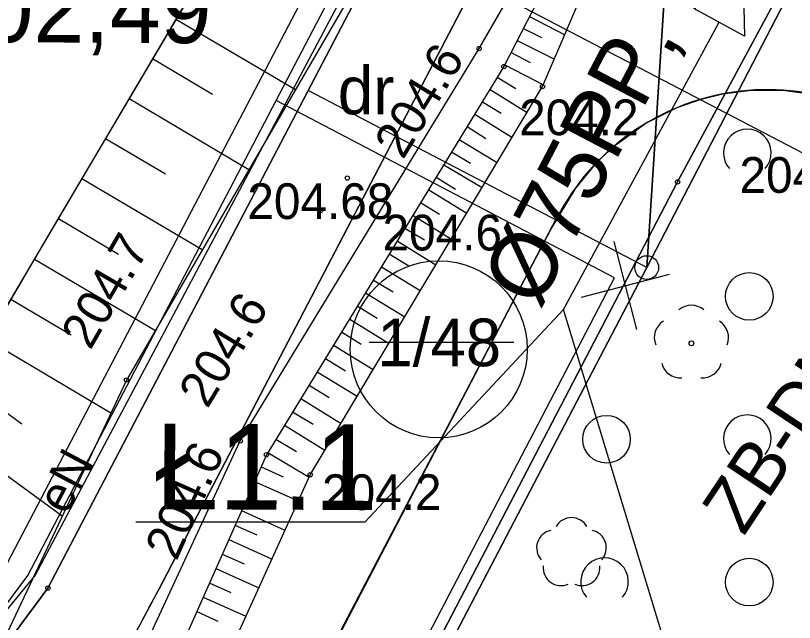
# Model space of a CAD drawing. Extents: x 6512606 to 6513006, y 6022524 to 6022728.
# Drawn here: x 6512715.61 to 6512731.97, y 6022586.93 to 6022599.67 of the extents above; entities that cross this region are included whole.
import ezdxf

# ---------------------------------------------------------------- set-up
doc = ezdxf.new("R2010")
doc.units = 0
for name, color, linetype in [('000 Inne (niezydentyfikowane)', 7, 'Continuous'), ('20', 7, 'Continuous'), ('202-punkt graniczny', 7, 'Continuous'), ('203-punkt graniczny', 7, 'Continuous'), ('210-oznaczenie konturu użytku gruntowego', 7, 'Continuous'), ('211-numer działki ewidencyjnej', 7, 'Continuous'), ('217-kontur klasyfikacyjny', 7, 'Continuous'), ('218-kontur użytku gruntowego', 7, 'Continuous'), ('219-działka ewidencyjna', 7, 'Continuous'), ('3', 7, 'Continuous'), ('4', 7, 'Continuous'), ('6', 7, 'Continuous'), ('926-Drzewo liściaste niepomierzone', 7, 'Continuous'), ('Default', 7, 'Continuous'), ('drzewo liściaste (punkt)', 7, 'Continuous'), ('E_OSW_KABLE', 7, 'Continuous'), ('jezdnia', 7, 'Continuous'), ('kolor_kostka_bet', 7, 'Continuous'), ('kolor_sc_rowerowa', 7, 'Continuous'), ('Level 47', 7, 'Continuous'), ('maxp_kan_deszczowa', 7, 'Continuous'), ('maxp_likwidacje', 7, 'Continuous'), ('maxp_obrzeże', 7, 'Continuous'), ('maxp_ramka_2', 7, 'Continuous'), ('ogrodzenie trwałe', 7, 'Continuous'), ('pikieta naturalna', 7, 'Continuous'), ('pikieta naturalna-Atr2', 7, 'Continuous'), ('pikieta sztuczna', 7, 'Continuous'), ('pikieta sztuczna-Atr2', 7, 'Continuous'), ('przewód elektroenergetyczny (linia)', 7, 'Continuous'), ('przewód elektroenergetyczny (linia)-Atr1', 7, 'Continuous'), ('punkt wysokościowy naturalny', 7, 'Continuous'), ('punkt wysokościowy naturalny-Atr2', 7, 'Continuous'), ('skarpa nieumocniona', 7, 'Continuous'), ('zadrzewienie  zakrzewienie', 7, 'Continuous')]:
    doc.layers.add(name, color=color, linetype=linetype)

# ---------------------------------------------------------------- blocks, each defined once
blk = doc.blocks.new('203')
at = {"layer": 'Default'}
blk.add_circle((0, 0), 0.45, dxfattribs=at)
blk = doc.blocks.new('202')
at = {"layer": 'Default'}
blk.add_circle((0, 0), 2.5, dxfattribs=at)
blk = doc.blocks.new('PW01')
at = {"layer": 'Default'}
blk.add_circle((0, 0), 0.45, dxfattribs=at)
blk = doc.blocks.new('926')
at = {"layer": 'Default'}
for centre, start, end in [((0, 3.75), 30.147, 149.853), ((-3.57, 1.16), 102.147, 221.853), ((3.57, 1.16), 318.147, 77.853), ((-2.2, -3.03), 174.147, 293.853), ((2.2, -3.03), 246.147, 5.853)]:
    blk.add_arc(centre, 3.75, start, end, dxfattribs=at)
blk = doc.blocks.new('OP021')
at = {"layer": 'Default'}
blk.add_circle((0, 0), 0.5, dxfattribs=at)
for centre, start, end in [((0, 4), 49.272, 130.728), ((-3.8, 1.24), 121.308, 202.548), ((3.8, 1.24), 337.452, 58.692), ((-2.35, -3.24), 193.221, 274.871), ((2.35, -3.24), 265.129, 346.779)]:
    blk.add_arc(centre, 4, start, end, dxfattribs=at)
blk = doc.blocks.new('OTZK1')
at = {"layer": 'Default'}
blk.add_circle((0, 0), 5, dxfattribs=at)
blk = doc.blocks.new('OTZK2')
at = {"layer": 'Default'}
blk.add_arc((0, 0), 5, 318.85, 221.162, dxfattribs=at)

msp = doc.modelspace()

# ---------------------------------------------------------------- linework, layer by layer
msp.add_lwpolyline([(6512728.87, 6022594.38), (6512721.76, 6022598.101)])
at = {"layer": '000 Inne (niezydentyfikowane)'}
for p, q in [((6512718.98, 6022599.6), (6512721.49, 6022598.12)), ((6512718.49, 6022598.77), (6512719.75, 6022598.02)), ((6512718, 6022597.93), (6512720.51, 6022596.44)), ((6512717.5, 6022597.09), (6512718.76, 6022596.35)), ((6512717, 6022596.25), (6512719.53, 6022594.76)), ((6512716.51, 6022595.41), (6512717.77, 6022594.66)), ((6512716.01, 6022594.56), (6512718.55, 6022593.06)), ((6512715.51, 6022593.72), (6512716.78, 6022592.97)), ((6512715.01, 6022592.87), (6512717.61, 6022591.33)), ((6512714.43, 6022592.05), (6512715.74, 6022591.1)), ((6512713.81, 6022591.19), (6512716.59, 6022589.17))]:
    msp.add_line(p, q, dxfattribs=at)
for points in [[(6512726.41, 6022599.65), (6512727.15, 6022599.27)], [(6512726.28, 6022599.4), (6512726.66, 6022599.21)], [(6512726.15, 6022599.15), (6512726.93, 6022598.76)], [(6512726.02, 6022598.9), (6512726.42, 6022598.69)], [(6512725.89, 6022598.64), (6512726.7, 6022598.22)], [(6512725.73, 6022598.38), (6512726.12, 6022598.14)], [(6512725.58, 6022598.12), (6512726.36, 6022597.64)], [(6512725.42, 6022597.86), (6512725.81, 6022597.62)], [(6512725.26, 6022597.6), (6512726.04, 6022597.12)], [(6512725.1, 6022597.34), (6512725.49, 6022597.09)], [(6512724.93, 6022597.07), (6512725.73, 6022596.59)], [(6512724.77, 6022596.81), (6512725.17, 6022596.57)], [(6512724.61, 6022596.54), (6512725.41, 6022596.06)], [(6512724.45, 6022596.28), (6512724.85, 6022596.03)], [(6512724.29, 6022596.01), (6512725.09, 6022595.52)], [(6512724.12, 6022595.75), (6512724.52, 6022595.5)], [(6512723.96, 6022595.48), (6512724.77, 6022594.98)], [(6512723.79, 6022595.21), (6512724.2, 6022594.96)], [(6512723.63, 6022594.94), (6512724.44, 6022594.44)], [(6512723.46, 6022594.67), (6512723.87, 6022594.42)], [(6512723.3, 6022594.4), (6512724.11, 6022593.9)], [(6512723.13, 6022594.12), (6512723.54, 6022593.87)], [(6512722.96, 6022593.85), (6512723.79, 6022593.35)], [(6512722.79, 6022593.58), (6512723.21, 6022593.32)], [(6512722.63, 6022593.3), (6512723.46, 6022592.79)], [(6512722.46, 6022593.03), (6512722.87, 6022592.77)], [(6512722.29, 6022592.75), (6512723.12, 6022592.24)], [(6512722.12, 6022592.47), (6512722.54, 6022592.21)], [(6512721.95, 6022592.19), (6512722.79, 6022591.68)], [(6512721.78, 6022591.91), (6512722.2, 6022591.65)], [(6512721.6, 6022591.63), (6512722.45, 6022591.11)], [(6512721.43, 6022591.35), (6512721.86, 6022591.09)], [(6512721.26, 6022591.07), (6512722.11, 6022590.55)], [(6512721.08, 6022590.78), (6512721.51, 6022590.52)], [(6512720.91, 6022590.5), (6512721.78, 6022589.98)], [(6512720.77, 6022590.2), (6512721.23, 6022589.99)], [(6512720.63, 6022589.89), (6512721.55, 6022589.48)], [(6512720.49, 6022589.58), (6512720.95, 6022589.38)], [(6512720.36, 6022589.28), (6512721.27, 6022588.87)], [(6512720.22, 6022588.97), (6512720.68, 6022588.77)], [(6512720.09, 6022588.67), (6512721, 6022588.26)], [(6512719.95, 6022588.36), (6512720.41, 6022588.16)], [(6512719.82, 6022588.06), (6512720.72, 6022587.66)], [(6512719.68, 6022587.76), (6512720.13, 6022587.56)], [(6512719.55, 6022587.46), (6512720.45, 6022587.06)], [(6512719.42, 6022587.16), (6512719.86, 6022586.96)]]:
    msp.add_lwpolyline(points, dxfattribs=at)
at = {"layer": '20'}
for p, q in [((6512727.123, 6022593.499), (6512722.95, 6022589.032)), ((6512722.95, 6022589.032), (6512718.139, 6022589.032))]:
    msp.add_line(p, q, dxfattribs=at)
at = {"layer": '217-kontur klasyfikacyjny'}
for points in [[(6512716.29, 6022587.65), (6512727.91, 6022609.85)], [(6512735.75, 6022607.64), (6512728.87, 6022594.38)], [(6512728.87, 6022594.38), (6512723.14, 6022583.41)], [(6512706.28, 6022574.16), (6512716.29, 6022587.65)]]:
    msp.add_lwpolyline(points, dxfattribs=at)
at = {"layer": '218-kontur użytku gruntowego'}
for points in [[(6512728.87, 6022594.38), (6512731.57, 6022636.01)], [(6512731.57, 6022636.01), (6512728.87, 6022594.38)], [(6512727.91, 6022609.85), (6512716.29, 6022587.65)], [(6512716.29, 6022587.65), (6512727.91, 6022609.85)], [(6512735.75, 6022607.64), (6512728.87, 6022594.38)], [(6512728.87, 6022594.38), (6512735.75, 6022607.64)], [(6512728.87, 6022594.38), (6512723.14, 6022583.41)], [(6512723.14, 6022583.41), (6512728.87, 6022594.38)], [(6512716.29, 6022587.65), (6512706.28, 6022574.16)], [(6512706.28, 6022574.16), (6512716.29, 6022587.65)]]:
    msp.add_lwpolyline(points, dxfattribs=at)
at = {"layer": '219-działka ewidencyjna'}
for points in [[(6512728.87, 6022594.38), (6512732.3, 6022647.29)], [(6512716.29, 6022587.65), (6512727.91, 6022609.85)], [(6512735.75, 6022607.64), (6512728.87, 6022594.38)], [(6512728.87, 6022594.38), (6512721.76, 6022598.101)], [(6512723.14, 6022583.41), (6512728.87, 6022594.38)], [(6512706.28, 6022574.16), (6512716.29, 6022587.65)]]:
    msp.add_lwpolyline(points, dxfattribs=at)
at = {"layer": '3'}
msp.add_line((6512723.038, 6022592.812), (6512726.077, 6022592.812), dxfattribs=at)
at = {"layer": '4'}
for points in [[(6512728.87, 6022594.38), (6512732.3, 6022647.29)], [(6512716.29, 6022587.65), (6512727.91, 6022609.85)], [(6512735.75, 6022607.64), (6512728.87, 6022594.38)], [(6512723.14, 6022583.41), (6512728.87, 6022594.38)], [(6512706.28, 6022574.16), (6512716.29, 6022587.65)]]:
    msp.add_lwpolyline(points, dxfattribs=at)
at = {"layer": '6'}
msp.add_circle((6512724.502, 6022592.665), 1.859, dxfattribs=at)
at = {"layer": 'E_OSW_KABLE'}
msp.add_lwpolyline([(6512724.836, 6022600.607), (6512735.232, 6022595.177), (6512735.232, 6022595.177)], dxfattribs=at)
at = {"layer": 'jezdnia'}
msp.add_lwpolyline([(6512731.08, 6022620.65), (6512728.82, 6022611.46), (6512722.83, 6022600.42), (6512717.94, 6022592.02), (6512712.43, 6022580.37), (6512709.04, 6022573), (6512712.21, 6022570.83), (6512715.01, 6022579.3), (6512720.33, 6022590.74), (6512725.35, 6022598.98), (6512731.85, 6022610.22), (6512735.75, 6022620.3)], close=True, dxfattribs=at)
at = {"layer": 'kolor_kostka_bet'}
msp.add_line((6512726.985, 6022595.432), (6512721.987, 6022585.864), dxfattribs=at)
for points in [[(6512708.915, 6022572.782), (6512706.28, 6022574.16), (6512716.29, 6022587.65), (6512727.91, 6022609.85), (6512731.23, 6022647.88), (6512731.197, 6022649.415), (6512729.023, 6022649.531)], [(6512729.023, 6022649.531), (6512731.197, 6022649.415), (6512731.23, 6022647.88), (6512727.91, 6022609.85), (6512716.29, 6022587.65), (6512706.28, 6022574.16), (6512708.915, 6022572.782)], [(6512718.619, 6022587.623), (6512719.35, 6022589.023), (6512723.817, 6022597.575), (6512727.095, 6022603.851), (6512728.84, 6022607.192), (6512729.199, 6022607.879)]]:
    msp.add_lwpolyline(points, dxfattribs=at)
for centre, radius, start, end in [((6512731.417, 6022593.117), 5, 44.1446, 152.4212), ((6512675.984, 6022609.892), 48.1, 324.6359, 332.4212)]:
    msp.add_arc(centre, radius, start, end, dxfattribs=at)
at = {"layer": 'kolor_sc_rowerowa'}
for points in [[(6512729.199, 6022607.879), (6512728.84, 6022607.192), (6512727.095, 6022603.851), (6512723.817, 6022597.575), (6512719.35, 6022589.023), (6512718.619, 6022587.623)], [(6512721.987, 6022585.864), (6512726.985, 6022595.432)]]:
    msp.add_lwpolyline(points, dxfattribs=at)
for centre, radius, start, end in [((6512731.417, 6022593.117), 5, 44.1437, 152.4212), ((6512675.984, 6022609.892), 48.1, 324.6359, 332.4212)]:
    msp.add_arc(centre, radius, start, end, dxfattribs=at)
at = {"layer": 'maxp_kan_deszczowa'}
for points in [[(6512725.335, 6022612.434), (6512724.242, 6022610.122), (6512720.701, 6022602.625), (6512720.201, 6022601.66), (6512719.972, 6022601.269), (6512719.97, 6022601.276), (6512719.518, 6022600.503), (6512718.485, 6022598.756), (6512717.786, 6022597.573), (6512717.004, 6022596.25), (6512716.459, 6022595.327), (6512716.038, 6022594.614), (6512715.257, 6022593.294), (6512714.873, 6022592.662), (6512714.556, 6022592.225), (6512713.769, 6022591.139), (6512713.152, 6022590.289), (6512712.768, 6022589.76), (6512711.747, 6022588.353), (6512710.95, 6022587.254), (6512708.754, 6022584.227)], [(6512729.365, 6022586.121), (6512727.123, 6022593.499), (6512730.393, 6022599.532)], [(6512721.429, 6022584.824), (6512726.855, 6022595.183), (6512727.382, 6022596.051), (6512727.851, 6022596.623), (6512728.224, 6022596.957), (6512728.852, 6022597.41), (6512729.511, 6022597.74), (6512730.014, 6022597.917), (6512730.469, 6022598.027), (6512731.064, 6022598.105), (6512731.729, 6022598.107), (6512732.446, 6022598.01)]]:
    msp.add_lwpolyline(points, dxfattribs=at)
msp.add_lwpolyline([(6512729.86, 6022599.821), (6512730.894, 6022600.455), (6512730.926, 6022599.243)], close=True, dxfattribs=at)
at = {"layer": 'maxp_likwidacje'}
for p, q in [((6512728.661, 6022593.078), (6512728.184, 6022594.926)), ((6512727.498, 6022593.763), (6512729.347, 6022594.241))]:
    msp.add_line(p, q, dxfattribs=at)
at = {"layer": 'maxp_obrzeże'}
for p, q in [((6512718.619, 6022587.623), (6512729.199, 6022607.879)), ((6512721.987, 6022585.863), (6512726.985, 6022595.432))]:
    msp.add_line(p, q, dxfattribs=at)
for centre, radius, start, end in [((6512731.417, 6022593.117), 5, 44.1437, 152.4212), ((6512675.984, 6022609.892), 48.1, 327.0219, 332.4212)]:
    msp.add_arc(centre, radius, start, end, dxfattribs=at)
at = {"layer": 'maxp_ramka_2'}
for p, q in [((6512728.196, 6022594.169), (6512721.086, 6022597.89)), ((6512722.462, 6022583.191), (6512728.196, 6022594.169))]:
    msp.add_line(p, q, dxfattribs=at)
for points in [[(6512721.086, 6022597.89), (6512727.421, 6022609.993), (6512730.73, 6022647.896), (6512730.304, 6022667.864), (6512724.475, 6022673.519)], [(6512704.78, 6022573.816), (6512715.44, 6022588.183), (6512724.41, 6022605.32)], [(6512705.53, 6022573.988), (6512715.865, 6022587.917), (6512721.086, 6022597.89)]]:
    msp.add_lwpolyline(points, dxfattribs=at)
at = {"layer": 'ogrodzenie trwałe'}
msp.add_lwpolyline([(6512755.94, 6022562.73), (6512746.11, 6022568.85), (6512734.85, 6022575.76), (6512722.94, 6022583.56), (6512729.52, 6022596.18), (6512735.87, 6022607.95), (6512736.94, 6022619.99)], dxfattribs=at)
at = {"layer": 'przewód elektroenergetyczny (linia)'}
msp.add_lwpolyline([(6512726.13, 6022606.96), (6512716.02, 6022587.92), (6512710.36, 6022581.04), (6512708.56, 6022578.24), (6512706.34, 6022574.34), (6512697.643, 6022555.92)], dxfattribs=at)
at = {"layer": 'skarpa nieumocniona'}
for points in [[(6512728.82, 6022611.46), (6512722.83, 6022600.42), (6512717.94, 6022592.02), (6512712.43, 6022580.37), (6512701.7, 6022566.06), (6512698.57, 6022561.61), (6512695.94, 6022556.8), (6512692.31, 6022558.67), (6512695.23, 6022563.7), (6512698.61, 6022570.74), (6512708.72, 6022584.18), (6512714.93, 6022592.74), (6512720.42, 6022602.03), (6512725.72, 6022613.25), (6512727.1, 6022620.51), (6512731.08, 6022620.65)], [(6512728.82, 6022611.46), (6512722.83, 6022600.42), (6512717.94, 6022592.02), (6512712.43, 6022580.37), (6512701.7, 6022566.06), (6512698.57, 6022561.61), (6512695.94, 6022556.8), (6512692.31, 6022558.67), (6512695.23, 6022563.7), (6512698.61, 6022570.74), (6512708.72, 6022584.18), (6512714.93, 6022592.74), (6512720.42, 6022602.03), (6512725.72, 6022613.25), (6512727.1, 6022620.51), (6512731.08, 6022620.65)], [(6512731.85, 6022610.22), (6512725.87, 6022598.6), (6512720.88, 6022590.45), (6512715.64, 6022578.67), (6512716.84, 6022579.11), (6512721.8, 6022590.03), (6512726.68, 6022598.18)], [(6512731.85, 6022610.22), (6512725.87, 6022598.6), (6512720.88, 6022590.45), (6512715.64, 6022578.67), (6512716.84, 6022579.11), (6512721.8, 6022590.03), (6512726.68, 6022598.18)]]:
    msp.add_lwpolyline(points, close=True, dxfattribs=at)
at = {"layer": 'zadrzewienie  zakrzewienie'}
msp.add_lwpolyline([(6512735.87, 6022607.95), (6512729.52, 6022596.18), (6512722.94, 6022583.56), (6512734.85, 6022575.76)], dxfattribs=at)

# ---------------------------------------------------------------- block references
at = {"layer": '202-punkt graniczny', "xscale": 0.1, "yscale": 0.10000000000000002}
msp.add_blockref('202', (6512728.87, 6022594.38), dxfattribs=at)
at = {"layer": '203-punkt graniczny', "xscale": 0.1, "yscale": 0.10000000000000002}
msp.add_blockref('203', (6512716.29, 6022587.65), dxfattribs=at)
at = {"layer": '926-Drzewo liściaste niepomierzone', "xscale": 0.1, "yscale": 0.10000000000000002}
msp.add_blockref('926', (6512727.29, 6022588.38), dxfattribs=at)
at = {"layer": 'drzewo liściaste (punkt)', "xscale": 0.1, "yscale": 0.10000000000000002}
msp.add_blockref('OP021', (6512729.81, 6022592.79), dxfattribs=at)
at = {"layer": 'pikieta naturalna', "xscale": 0.1, "yscale": 0.10000000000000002}
for p in [(6512725.35, 6022598.98), (6512725.87, 6022598.6), (6512726.68, 6022598.18), (6512729.52, 6022596.18), (6512717.94, 6022592.02), (6512720.33, 6022590.74), (6512720.88, 6022590.45), (6512721.8, 6022590.03)]:
    msp.add_blockref('PW01', p, dxfattribs=at)
at = {"layer": 'pikieta sztuczna', "xscale": 0.1, "yscale": 0.10000000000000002}
msp.add_blockref('PW01', (6512722.58, 6022596.26), dxfattribs=at)
at = {"layer": 'punkt wysokościowy naturalny', "xscale": 0.1, "yscale": 0.10000000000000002}
msp.add_blockref('PW01', (6512722.02, 6022595.58), dxfattribs=at)
at = {"layer": 'zadrzewienie  zakrzewienie', "xscale": 0.1, "yscale": 0.10000000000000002}
for name, p in [('OTZK2', (6512730.984, 6022596.787)), ('OTZK1', (6512731.026, 6022593.776)), ('OTZK1', (6512728.026, 6022590.776)), ('OTZK2', (6512730.984, 6022590.787)), ('OTZK2', (6512727.984, 6022587.787)), ('OTZK1', (6512731.026, 6022587.776))]:
    msp.add_blockref(name, p, dxfattribs=at)

# ---------------------------------------------------------------- texts
at = {"layer": '210-oznaczenie konturu użytku gruntowego'}
msp.add_text('dr', height=1, dxfattribs=at).set_placement((6512722.38, 6022597.6))
at = {"layer": '211-numer działki ewidencyjnej'}
msp.add_text('1/48', height=1, dxfattribs=at).set_placement((6512723.21, 6022592.31))
at = {"layer": '4'}
msp.add_text('1/48', height=1, dxfattribs=at).set_placement((6512723.21, 6022592.31))
at = {"layer": 'Level 47'}
for s, height, rotation, p in [('%%c75PP, L=73,1m', 1.3824, 62.3574, (6512726.582, 6022593.48)), ('202,49', 1.4377, 359.7281, (6512713.845, 6022599.12)), ('ZB-DN1600', 1.1134, 56.3241, (6512730.909, 6022588.727)), ('Ł1.1', 1.7971, 359.7281, (6512718.536, 6022589.309))]:
    msp.add_text(s, height=height, rotation=rotation, dxfattribs=at).set_placement(p)
at = {"layer": 'pikieta naturalna-Atr2'}
for s, rotation, p in [('204.6', 58.522, (6512723.75, 6022596.63)), ('204.7', 59.794, (6512717.18, 6022592.63)), ('204.6', 58.649, (6512719.64, 6022591.4)), ('204.6', 66.019, (6512718.99, 6022588.2))]:
    msp.add_text(s, height=0.75, rotation=rotation, dxfattribs=at).set_placement(p)
for s, p in [('204.2', (6512726.19, 6022597.16)), ('204.1', (6512730.82, 6022595.95)), ('204.2', (6512722.05, 6022589.29))]:
    msp.add_text(s, height=0.75, dxfattribs=at).set_placement(p)
at = {"layer": 'pikieta sztuczna-Atr2'}
msp.add_text('204.68', height=0.75, dxfattribs=at).set_placement((6512720.48, 6022595.4))
at = {"layer": 'przewód elektroenergetyczny (linia)-Atr1'}
msp.add_text('eN', height=0.75, rotation=62.032, dxfattribs=at).set_placement((6512716.681, 6022589.165))
at = {"layer": 'punkt wysokościowy naturalny-Atr2'}
msp.add_text('204.6', height=0.75, dxfattribs=at).set_placement((6512723.32, 6022594.74))

doc.saveas('drawing.dxf')
